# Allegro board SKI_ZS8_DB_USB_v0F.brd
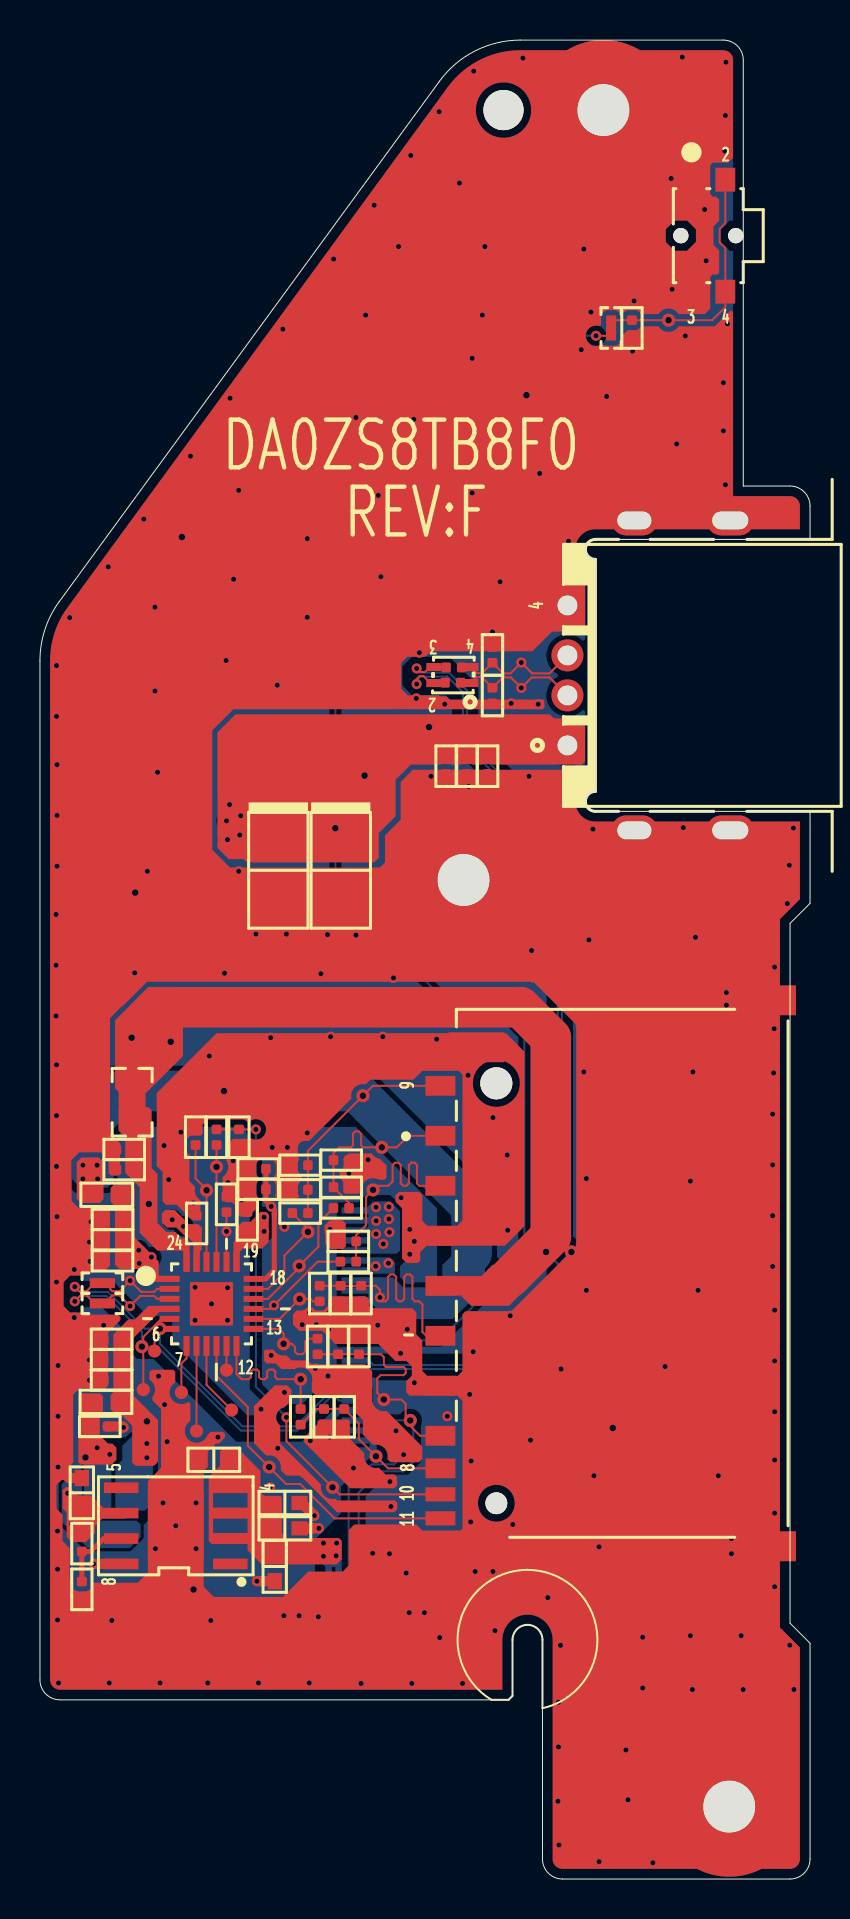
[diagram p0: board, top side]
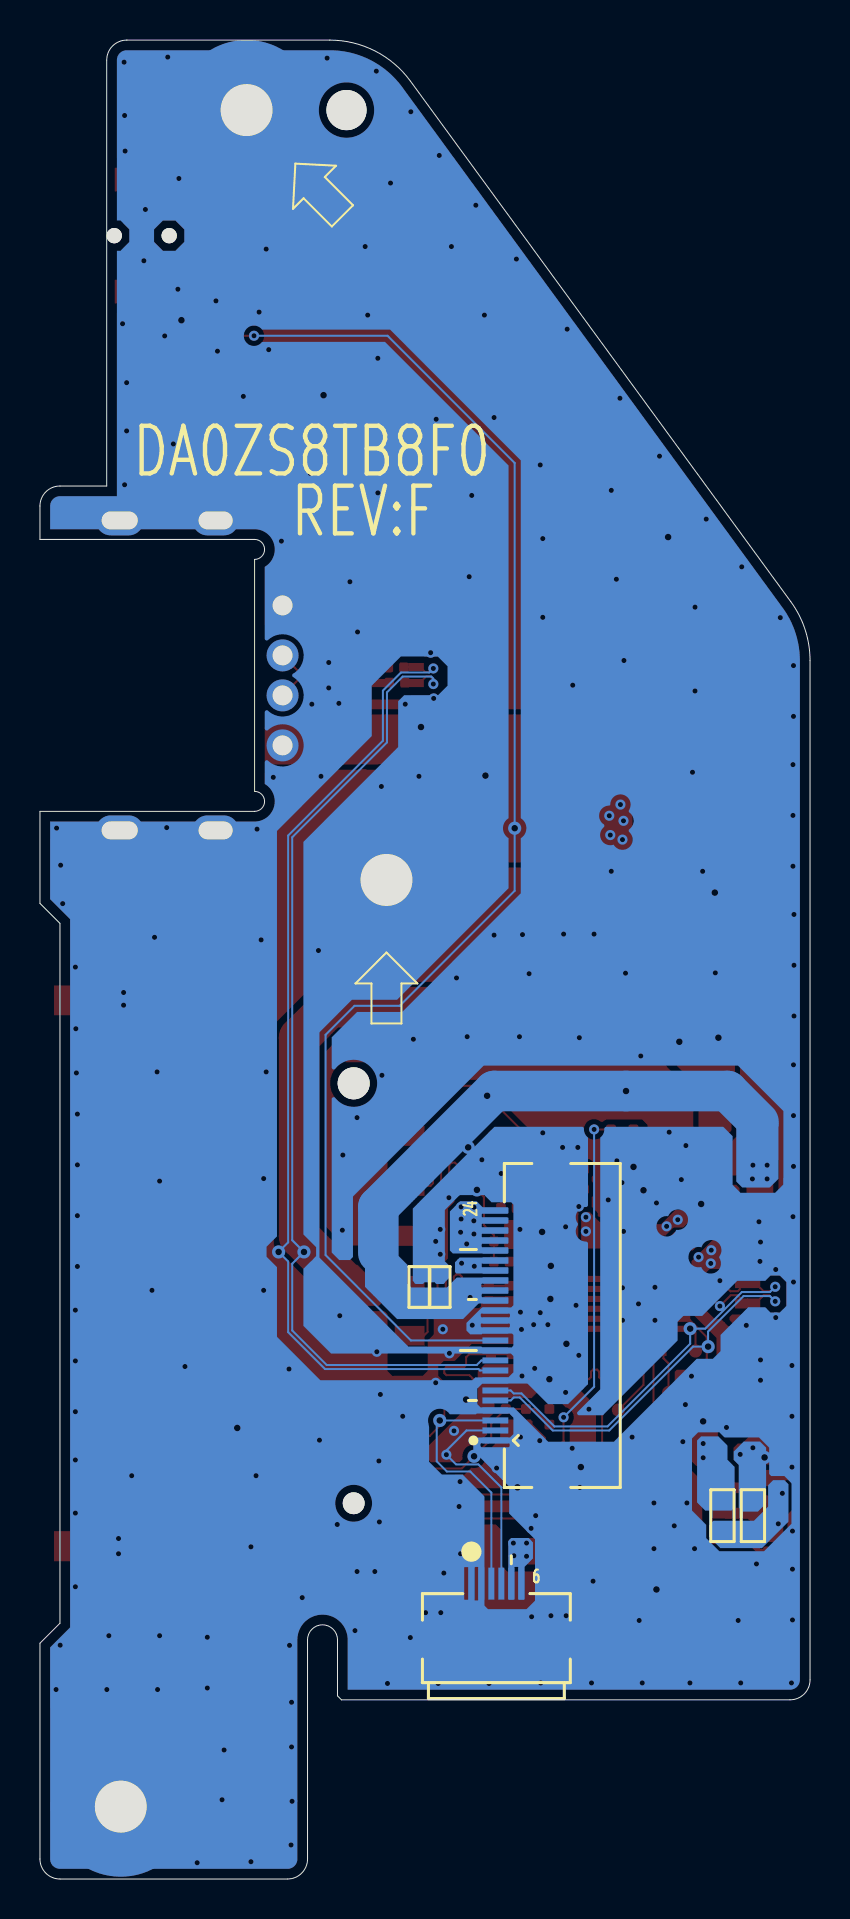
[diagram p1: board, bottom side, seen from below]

Outline 38.54 x 91.96 mm; copper layers: TOP, SGND, IN1, IN2, SVCC, IN3, SGND1, BOTTOM. Coordinates in mm from the lower left corner of the outline.
Outline path: 0,60.93 arc(0.25,62.48) 0.96,63.88 20,89.91 arc(21.77,91.42) 24.04,91.96 34.2,91.96 arc(34.91,91.67) 35.2,90.96 35.2,69.66 37.54,69.66 arc(38.25,69.37) 38.54,68.66 38.54,66.99 27.8,66.99 arc(27.3,66.49) 27.8,65.99 27.8,54.39 arc(27.3,53.89) 27.8,53.39 38.54,53.39 38.54,48.79 37.54,47.79 37.54,12.79 38.54,11.79 38.54,1 arc(38.25,0.29) 37.54,0 26.15,0 arc(25.44,0.29) 25.15,1 25.15,11.96 arc(24.4,12.71) 23.65,11.96 23.65,9.16 23.45,8.96 1,8.96 arc(0.29,9.25) 0,9.96 0,60.93

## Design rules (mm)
net group DFP-S4(4: nets USB2N7_CR USB2P7_CR
net group W4-T1B: nets SD_CLK SD_CMD SD_D0 SD_D1 SD_D2 SD_D3 SD_WP
net group W20-T123B: nets +3V3 +3V3_CR +3V3_CR_A +5V +5V_S5_USB2 VCC_SD

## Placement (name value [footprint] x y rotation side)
C1  470p/50v_4  [CC0402]  22.41 55.65 270 top
C2  0.1u/10v_4  [CC0402]  21.37 55.65 270 top
C3  150u/6.3v_3528  [CC3528]  11.93 50.44 90 top
C4  1u/6.3v_4  [CC0402]  20.32 55.65 90 top
C6  1u/16v_6  [CC0603]  8.7 20.96 180 top
C7  10u/6.3v_6  [CC0603]  12.26 17.54 0 top
C8  0.1u/50v_6  [CC0603]  12.26 18.81 0 top
C9  *0.1u/50v_6  [CC0603]  11.75 15.63 270 top
C10  10u/6.3v_6  [CC0603]  2.1 19.31 90 top
C5235  *10u/6.3v_4  [CC0402]  18.52 29.6 270 bottom
C5236  *2.2u/10v_4  [CC0402]  19.56 29.6 270 bottom
C5237  4.7u/6.3v_4  [CC0402]  3.63 31.97 0 top
C5238  0.1u/10v_4  [CC0402]  3.63 30.91 0 top
C5239  10u/6.3v_4  [CC0402]  3.63 32.98 0 top
C5240  0.1u/10v_4  [CC0402]  10.38 32.96 270 top
C5241  0.1u/10v_4  [CC0402]  7.84 32.78 270 top
C5242  2.2u/10v_4  [CC0402]  3.58 25.97 0 top
C5243  0.1u/10v_4  [CC0402]  3.58 26.99 0 top
C5244  1u/6.3v_4  [CC0402]  10.92 34.49 0 top
C5245  4.7u/6.3v_4  [CC0402]  4.22 35.47 0 top
C5246  0.1u/10v_4  [CC0402]  7.79 37.1 90 top
C5247  2.7p/50v_4  [CC0402]  16.07 29.28 90 top
C5248  0.1u/10v_4  [CC0402]  4.22 36.49 0 top
C5548  2.7p/50v_4  [CC0402]  15.97 26.63 270 top
C5549  2.7p/50v_4  [CC0402]  15.23 23.11 90 top
C5550  2.7p/50v_4  [CC0402]  13.02 35.7 0 top
C5551  2.7p/50v_4  [CC0402]  15.08 35.95 180 top
C5552  *150u/6.3v_3528  [CC3528]  15.05 50.44 90 top
C5553  68p/50v_4  [CC0402]  10.92 35.51 0 top
C5554  68p/50v_4  [CC0402]  3.58 24.95 180 top
C5555  68p/50v_4  [CC0402]  3 22.63 0 top
CN1  c14743-10409-l  [USB-C14743-10409-L-4P-L]  34.55 60.19 90 top
CN17  sd-card  [SDCARD-PSDAT4-09GLBS1NN4H0-11P]  22.84 30.29 90 top
CN5027  196033-06021-3  [AF706L-A2G1T-6P-L-SMT]  15.7 11.97 180 bottom
CN5046  usb db  [50501-02401-001-24P-L]  12.95 27.68 90 bottom
D1  *5v/0.2p_4  [CC0402]  22.65 59.18 90 top
D2  *5v/0.2p_4  [CC0402]  22.65 61.21 270 top
D9  *vport 0402 151 mv05  [RC0402]  29.63 77.56 90 top
D5006  *0.2pf/5v_4  [RC0402]  14.93 26.63 90 top
D5007  *0.2pf/5v_4  [RC0402]  14.21 23.11 270 top
D5008  *0.2pf/5v_4  [RC0402]  13.02 34.47 180 top
D5009  *0.2pf/5v_4  [RC0402]  15.08 34.59 0 top
D5010  *0.2pf/5v_4  [RC0402]  15.04 29.28 270 top
D5011  *0.2pf/5v_4  [RC0402]  15.43 31.89 180 top
D5012  *0.2pf/5v_4  [RC0402]  9.96 37.1 270 top
HOLE1  *h-c276d102p2  [H-C276D102P2]  28.2 88.46 180 bottom
HOLE2  *h-c276d102p2  [H-C276D102P2]  21.2 49.96 180 bottom
HOLE3  *h-c276d102p2  [H-C276D102P2]  34.5 3.62 0 top
HOLE4  * h-c79d79n  [H-C79D79N]  23.2 88.46 0 top
L1  mcm2012b900gbe/0.4a/90  [FILTER-MCM2012B900GBE-4P]  20.64 60.21 180 top
L5009  120ohm_2a_6  [RC0603]  3.3 23.86 180 top
NOREF  -  []  -32.21 -79.31 0 top
NOREF#2  -  []  18.59 -38.67 0 top
R1  *0_4  [RC0402]  20.67 59.83 180 top
R2  *0_4  [RC0402]  20.72 60.59 180 top
R3  31.6k/f_4  [RC0402]  2.1 14.49 90 top
R10  *short_8  [SHORT0805]  4.61 38.85 270 top
R12  *short_4  [SHORT0402]  28.59 77.56 270 top
R429  *0_6  [RC0603]  4.38 18.17 90 bottom
R5686  *0_6  [RC0603]  3.34 34.21 0 top
R5690  *short_4  [SHORT0402]  3.13 28.78 0 top
R5691  *short_4  [SHORT0402]  3.13 29.8 0 top
R5692  90.9_4  [RC0402]  13.89 26.63 270 top
R5698  33_4  [RC0402]  8.84 37.1 90 top
R6005  90.9_4  [RC0402]  13.05 23.11 270 top
R6006  90.9_4  [RC0402]  13.02 33.3 0 top
R6007  90.9_4  [RC0402]  15.08 33.55 0 top
R6008  90.9_4  [RC0402]  15.43 30.87 0 top
R6009  90.9_4  [RC0402]  14 29.28 90 top
R6010  *0_4  [RC0402]  9.34 33.74 90 top
R6011  0_6  [RC0603]  2.86 18.17 90 bottom
R6013  100k/f_4  [RC0402]  2.1 16.77 90 top
SW1  power switch  [SW-NTC316-AA1G-A160T-4P]  33.45 82.18 0 top
TP5150  *pad  [TP2675]  5.17 24.47 90 top
TP5151  *pad  [TP2675]  5.73 26.41 90 top
TP5152  *pad  [TP2675]  7.08 24.33 90 top
TP5153  *pad  [TP2675]  7.84 22.4 90 top
TP5154  *pad  [TP2675]  9.59 23.45 90 top
TP5155  *pad  [TP2675]  9.34 25.45 90 top
U1  g9661-25adjf12u  [SOP8-6-1_27-9P]  6.8 17.66 90 top
U5036  gl834l  [QFN24-4X4-5-25P-1H]  8.59 28.76 0 top

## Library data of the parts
C1 C2 C4 C5235-C5248 C5548-C5551 C5553-C5555 D1 D2 = CC0402
C3 C5552 = CC3528
C6-C10 = CC0603
CN1 = USB-C14743-10409-L-4P-L
CN17 = SDCARD-PSDAT4-09GLBS1NN4H0-11P
CN5027 = AF706L-A2G1T-6P-L-SMT
CN5046 = 50501-02401-001-24P-L
D9 D5006-D5012 R1-R3 R5692 R5698 R6005-R6010 R6013 = RC0402
HOLE1-HOLE3 = H-C276D102P2
HOLE4 = H-C79D79N
L1 = FILTER-MCM2012B900GBE-4P
L5009 R429 R5686 R6011 = RC0603
R10 = SHORT0805
R12 R5690 R5691 = SHORT0402
SW1 = SW-NTC316-AA1G-A160T-4P
TP5150-TP5155 = TP2675
U1 = SOP8-6-1_27-9P
U5036 = QFN24-4X4-5-25P-1H

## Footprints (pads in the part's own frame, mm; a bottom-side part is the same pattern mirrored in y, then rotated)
50501-02401-001-24P-L
  rect 0.305x1.295 smd: 1(-5.75,2.8) 2(-5.25,2.8) 3(-4.75,2.8) 4(-4.25,2.8) 5(-3.75,2.8) 6(-3.25,2.8) 7(-2.75,2.8) 8(-2.25,2.8) 9(-1.75,2.8) 10(-1.25,2.8) 11(-0.75,2.8) 12(-0.25,2.8) 13(0.25,2.8) 14(0.75,2.8) 15(1.25,2.8) 16(1.75,2.8) 17(2.25,2.8) 18(2.75,2.8) 19(3.25,2.8) 20(3.75,2.8) 21(4.25,2.8) 22(4.75,2.8) 23(5.25,2.8) 24(5.75,2.8)
  rect 1.803x1.397 smd: 25(-7.4,0) 26(7.4,0)
AF706L-A2G1T-6P-L-SMT
  rect 0.305x1.6 smd: 1(-1.25,2.8) 2(-0.75,2.8) 3(-0.25,2.8) 4(0.25,2.8) 5(0.75,2.8) 6(1.25,2.8)
  rect 1.803x1.397 smd: 7(-2.9,0) 8(2.9,0)
CC0402
  custom 0.12x0.12 smd: 1(0.39,0) 2(-0.39,0)
CC0603
  rect 0.813x0.711 smd: 1(0.737,0) 2(-0.737,0)
CC3528
  rect 2.032x2.413 smd: 1(1.6,0) 2(-1.6,0)
FILTER-MCM2012B900GBE-4P
  rect 0.762x0.406 smd: 1(-0.925,0.4) 2(0.925,0.4) 3(0.925,-0.4) 4(-0.925,-0.4)
H-C79D79N
  round 2.007 hole 2.007 unplated: (0,0)
H-C276D102P2
  round 7.01 hole 2.591: 1(0,0)
QFN24-4X4-5-25P-1H
  rect 0.991x0.305 smd: 1(-2.1,1.25) 2(-2.1,0.75) 3(-2.1,0.25) 4(-2.1,-0.25) 5(-2.1,-0.75) 6(-2.1,-1.25) 13(2.1,-1.25) 14(2.1,-0.75) 15(2.1,-0.25) 16(2.1,0.25) 17(2.1,0.75) 18(2.1,1.25)
  rect 0.305x0.991 smd: 7(-1.25,-2.1) 8(-0.75,-2.1) 9(-0.25,-2.1) 10(0.25,-2.1) 11(0.75,-2.1) 12(1.25,-2.1) 19(1.25,2.1) 20(0.75,2.1) 21(0.25,2.1) 22(-0.25,2.1) 23(-0.75,2.1) 24(-1.25,2.1)
  rect 2.159x2.159 smd: 25(0,0)
RC0402
  custom 0.12x0.12 smd: 1(0.39,0) 2(-0.39,0)
RC0603
  rect 0.813x0.711 smd: 1(0.737,0) 2(-0.737,0)
SDCARD-PSDAT4-09GLBS1NN4H0-11P
  round 1.092 hole 1.092 unplated: (-11.5,0)
  round 1.6 hole 1.6 unplated: (9.5,0)
  rect 0.991x1.499 smd: 1(6.875,2.8) 2(4.375,2.8) 3(1.875,2.8) 4(-0.625,2.8) 5(-3.125,2.8) 6(-5.625,2.8) 7(-8.125,2.8) 8(-9.755,2.8) 9(9.375,2.8)
  rect 0.711x1.499 smd: 10(-11.055,2.8) 11(-12.255,2.8)
  rect 1.499x2.794 smd: 12(11.3,1) 13(-13.65,1) 14(13.65,-13.6) 15(-13.65,-13.6)
SHORT0402
  rect 0.648x0.5 smd: 1(-0.39,0) 2(0.39,0)
SHORT0805
  rect 1.397x1.346 smd: 1(0.895,0) 2(-0.895,0)
SOP8-6-1_27-9P
  rect 0.533x1.727 smd: 1(-1.905,-2.73) 2(-0.635,-2.73) 3(0.635,-2.73) 4(1.905,-2.73) 5(1.905,2.73) 6(0.635,2.73) 7(-0.635,2.73) 8(-1.905,2.73)
  rect 3.302x2.794 smd: 9(0,0)
SW-NTC316-AA1G-A160T-4P
  round 0.762 hole 0.762 unplated: (-1.375,0) (1.375,0)
  rect 0.991x1.194 smd: 1(-0.85,2.8) 2(0.85,2.8) 3(-0.85,-2.8) 4(0.85,-2.8)
TP2675
  round 0.66 smd: 1(0,0)
USB-C14743-10409-L-4P-L
  round 1.6 hole 0.991: 1(-3.5,8.15) 2(-1,8.15) 3(1,8.15) 4(3.5,8.15)
  oval 1.499x2.311 hole 0.889x1.702: 5(-7.75,4.8) 6(7.75,4.8)
  oval 1.499x2.388 hole 0.889x1.803: 7(-7.75,0) 8(7.75,0)

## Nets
+3V3: C5235.1 C5236.1 CN5046.15 CN5046.16 CN5046.17 R5686.2
+3V3_CR: C5237.1 C5238.1 C5239.1 C5240.1 C5241.1 C5555.2 L5009.1 R5686.1 R6011.1 U5036.1 U5036.19 U5036.23
+3V3_CR_A: C5242.1 C5243.1 C5554.2 L5009.2 R429.1 U5036.4
+5V: C6.2 C7.2 C8.2 C9.2 CN5027.5 CN5027.6 CN5046.18 CN5046.19 U1.2 U1.3 U1.4
+5V_S5_USB2: C1.2 C2.2 C3.1 C4.1 C5552.1 CN1.1 CN5046.20 CN5046.21 CN5046.22 CN5046.23 CN5046.24
GND: C1.1 C2.1 C3.2 C4.2 C6.1 C7.1 C8.1 C9.1 C10.1 C5235.2 C5236.2 C5237.2 C5238.2 C5239.2 C5240.2 C5241.2 C5242.2 C5243.2 C5244.2 C5245.2 C5246.1 C5247.2 C5248.2 C5548.2 C5549.2 C5550.2 C5551.2 C5552.2 C5553.2 C5554.1 C5555.1 CN1.4 CN1.5 CN1.6 CN1.7 CN1.8 CN17.3 CN17.6 CN17.12 CN17.13 CN17.14 CN17.15 CN5027.1 CN5027.2 CN5027.7 CN5027.8 CN5046.1 CN5046.4 CN5046.7 CN5046.10 CN5046.12 CN5046.13 CN5046.14 CN5046.25 CN5046.26 D1.2 D2.2 D9.2 D5006.1 D5007.1 D5008.1 D5009.1 D5010.1 D5011.1 D5012.1 HOLE1.1 HOLE2.1 HOLE3.1 R3.2 R6010.1 SW1.1 SW1.3 U1.8 U1.9 U5036.25
VCC_SD: C5245.1 C5248.1 R10.1 U5036.24
CR_GPIO0: R6010.2 U5036.20
CR_VDD18: C5244.1 C5553.1 U5036.18
EL_SCL_C: CN5027.3 CN5046.3
EL_SDA_C: CN5027.4 CN5046.2
NBSWON#: CN5046.11 R12.2
POWER_BUTTON_I_EC_C: D9.1 R12.1 SW1.2 SW1.4
SD_CD#: R5698.2 U5036.21
SD_CD#_R: CN17.10 D5012.2 R5698.1
SD_CLK: R6009.2 U5036.14
SD_CLK_R: C5247.1 CN17.5 D5010.2 R6009.1
SD_CMD: R6008.2 U5036.15
SD_CMD_R: CN17.2 D5011.2 R6008.1
SD_D0: R5692.2 U5036.13
SD_D0_R: C5548.1 CN17.7 D5006.2 R5692.1
SD_D1: R6005.2 U5036.12
SD_D1_R: C5549.1 CN17.8 D5007.2 R6005.1
SD_D2: R6006.2 U5036.17
SD_D2_R: C5550.1 CN17.9 D5008.2 R6006.1
SD_D3: R6007.2 U5036.16
SD_D3_R: C5551.1 CN17.1 D5009.2 R6007.1
SD_WP: CN17.11 U5036.10
TPM_RSTZ: C5246.2 U5036.22
USB2N3: CN5046.9 L1.2 R1.1
USB2N3_CN: CN1.2 D1.1 L1.1 R1.2
USB2N7: CN5046.6 R5691.1
USB2N7_CR: R5691.2 U5036.2
USB2P3: CN5046.8 L1.3 R2.1
USB2P3_CN: CN1.3 D2.1 L1.4 R2.2
USB2P7: CN5046.5 R5690.1
USB2P7_CR: R5690.2 U5036.3
N38313166: CN17.4 R10.2
N38331581: TP5150.1 U5036.5
N38331591: TP5151.1 U5036.6
N38331627: TP5153.1 U5036.8
N38331630: TP5152.1 U5036.7
N38331633: TP5154.1 U5036.9
N38365347: C10.2 R429.2 R6011.2 R6013.1 U1.6
N38365361: R3.1 R6013.2 U1.7
N3829075310: TP5155.1 U5036.11

Pads without a net: U1 1 5

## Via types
v1: diameter 0.508, hole 0.254, TOP to BOTTOM, 307 vias
v2: diameter 0.66, hole 0.33, TOP to BOTTOM, 34 vias

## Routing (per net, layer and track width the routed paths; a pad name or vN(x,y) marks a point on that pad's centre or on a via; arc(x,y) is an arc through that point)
+3V3: length 24.4
  BOTTOM w2.032: 2.58,37.86 4.13,39.4 v2(9.21,39.4) 15.81,39.4 21.6,33.61 21.6,31.3
  vias: v1(2.15,35.7) v1(2.15,35.01) v1(2.86,35.7) v1(2.89,35.01)
+3V3_CR:
  vias: v1(2.86,21.56) v1(3.5,21.23) v1(4.94,31.45) v1(4.97,30.78) v1(5.58,31.1) v1(6.62,32.97) v1(7.18,32.64) v1(11.22,33.1) v1(11.22,32.38) v2(2.28,21.08)
+3V3_CR_A:
  vias: v1(5.35,21.78) v1(5.35,21.07) v2(5.35,22.89)
+5V:
  vias: v1(14.19,16.8) v1(14.19,16.14) v1(14.85,16.8) v1(14.82,16.16) v1(16.8,30.64) v1(17.44,30.79)
+5V_S5_USB2:
  vias: v1(9.34,52.92) v1(9.39,51.98) v1(9.49,53.73) v1(10.05,53.17) v1(10,52.21) v1(16.82,33.59) v1(16.83,32.91) v1(16.82,32.25) v1(17.19,31.76) v1(17.46,33.61) v1(17.46,33) v1(17.49,32.34) v2(16.25,55.18) v2(19.47,57.61)
GND: length 6.5
  TOP w0.508: C9.1 v1(10.86,14.89) ; C5555.1 4.13,22.63 v1(4.18,22.58) ; v1(0.91,20.6) 1.45,20.05 C10.1 ; C7.1 v1(13.96,17.54) ; v1(13.73,18.17) 13.1,18.81 C8.1 ; U1.8 v1(2.68,15.76)
  vias: v1(0.83,60.68) v1(0.83,58.14) v1(0.8,48.23) v1(0.8,45.69) v1(0.8,43.15) v1(0.83,40.72) v1(0.83,38.18) v1(0.83,35.64) v1(0.83,29.85) v1(0.85,55.73) v1(0.85,53.19) v1(0.85,50.65) v1(0.85,33.12) v1(0.91,25.68) v1(0.91,23.14) v1(0.88,17.4) v1(0.88,15.49) v1(0.88,12.95) v1(0.93,9.8) v1(1.49,63.08) v1(1.72,30.48) v1(1.72,28.08) v1(2.48,31.85) v1(2.51,30.89) v1(2.48,25.96) v1(2.48,24.94) v1(2.56,32.87) v1(3.19,27.69) v1(3.42,65.62) v1(3.47,9.8) v1(3.6,12.93) v1(4.74,45.31) v1(5.2,68) v1(5.38,50.39) v1(5.76,63.6) v1(5.76,59.41) v1(5.78,16.52) v1(5.88,55.35) v1(5.93,25.15) v1(6.01,9.8) v1(6.21,36.68) v1(6.24,23.72) v1(6.16,18.81) v1(6.44,34.98) v1(6.37,21.87) v1(6.8,17.66) v1(7.05,37.35) v1(7.53,71.15) v1(7.69,33.81) v1(7.76,29.59) v1(7.76,27.94) v1(7.81,18.81) v1(7.81,16.52) v1(8.4,9.8) v1(8.47,41.16) v1(8.59,28.76) v1(8.55,12.93) v1(8.91,22.1) v1(9.24,45.3) v1(9.31,60.93) v1(9.41,34.82) v1(9.39,29.57) v1(9.39,27.94) v1(9.51,74.05) v1(9.69,65) v1(9.67,35.92) v1(9.95,69.44) v1(9.95,50.39) v1(10.1,33.96) v1(10.81,47.25) v1(10.94,9.8) v1(11.07,23.49) v1(11.55,42.07) v1(11.52,19.58) v1(11.62,36.59) v1(11.57,26.19) v1(11.88,59.7) v1(11.9,21.54) v1(12.16,77.5) v1(12.23,32.61) v1(12.23,24.33) v1(12.21,13.17) v1(12.33,47.25) v1(12.38,36.59) v1(12.97,13.17) v1(13.12,27.72) v1(13.38,67.03) v1(13.38,63.09) v1(13.38,37.31) v1(13.5,70.71) v1(13.5,28.32) v1(13.53,21.92) v1(13.48,9.8) v1(13.83,27.72) v1(13.78,25.54) v1(13.93,13.12) v1(14.06,45.27) v1(14.39,47.23) v1(14.44,27.48) v1(14.42,25.16) v1(14.54,42.12) v1(14.52,32.49) v1(14.49,28.35) v1(14.49,22.1) v1(14.7,81.01) v1(15.46,35.28) v1(15.69,20.55) v1(15.81,73.08) v1(15.81,47.2) v1(16.07,9.78) v1(16.3,78.21) v1(16.42,35.97) v1(16.73,83.7) v1(16.65,16.29) v1(16.93,69.19) v1(16.91,27.7) v1(17.06,65.13) v1(17.16,42.12) v1(17.52,19.87) v1(17.49,16.27) v1(17.57,18.63) v1(17.69,45.06) v1(17.82,22.41) v1(17.95,81.64) v1(18.07,34.07) v1(18.05,26.29) v1(18.33,15.3) v1(18.38,27.49) v1(18.51,32.49) v1(18.51,31.24) v1(18.48,13.32) v1(18.56,86.19) v1(18.61,9.78) v1(18.71,73) v1(18.73,31.89) v1(18.74,24.82) v1(18.84,59.04) v1(18.99,61.32) v1(19.24,13.32) v1(19.57,55.14) v1(19.85,42) v1(19.98,88.38) v1(20,12.07) v1(20.26,58.75) v1(20.39,23.14) v1(21,84.81) v1(21.15,9.78) v1(21.43,40.19) v1(21.45,54.64) v1(21.5,24.23) v1(21.63,76.05) v1(21.63,69.32) v1(21.58,20.9) v1(21.56,17.86) v1(21.71,90.41) v1(21.68,26.37) v1(21.78,15.38) v1(22.14,78.21) v1(22.27,81.64) v1(22.65,62.36) v1(22.67,38.07) v1(22.67,15.38) v1(22.77,12.42) v1(23.03,64.87) v1(23.38,36.2) v1(23.41,32.44) v1(23.54,28.17) v1(23.58,58.79) v1(23.66,17.73) v1(24.17,91.06) v1(24.48,55.14) v1(24.6,46.43) v1(24.55,21.95) v1(24.93,58.75) v1(25.01,70.29) v1(25.42,14.07) v1(25.95,8.84) v1(25.95,6.6) v1(25.92,3.89) v1(25.97,1.7) v1(26.08,25.5) v1(26.05,11.68) v1(26.46,66.9) v1(26.86,55.09) v1(27.09,76.48) v1(27.22,81.51) v1(27.22,40.36) v1(27.35,35.03) v1(27.35,29.44) v1(27.47,46.96) v1(27.58,78.36) v1(27.68,52.5) v1(27.73,20.17) v1(27.98,16.61) v1(27.98,0.86) v1(28.36,74.14) v1(29.33,6.45) v1(29.43,3.96) v1(29.73,78.92) v1(29.66,76.4) v1(30.17,12.09) v1(30.17,9.55) v1(30.67,0.81) v1(31.28,25.63) v1(31.59,85.04) v1(31.64,79.5) v1(31.87,71.76) v1(32.15,91.11) v1(32.2,52.58) v1(32.3,77.17) v1(32.55,34.9) v1(32.55,12.17) v1(32.68,40.36) v1(32.66,9.47) v1(32.81,47.09) v1(32.93,29.44) v1(33.26,83.49) v1(33.34,80.92) v1(33.95,20.17) v1(34.2,74.83) v1(34.2,72.42) v1(34.33,90.86) v1(34.31,88.19) v1(34.28,86.41) v1(34.31,69.72) v1(34.41,77.77) v1(34.36,44.33) v1(34.36,43.7) v1(34.61,17.03) v1(34.61,16.27) v1(35.09,12.17) v1(35.2,9.47) v1(36.74,42.52) v1(36.72,40.31) v1(36.67,38.25) v1(36.67,35.71) v1(36.67,33.17) v1(36.67,30.63) v1(36.77,45.6) v1(36.77,28.45) v1(36.77,25.91) v1(36.77,23.37) v1(36.77,20.95) v1(36.77,18.3) v1(36.77,14.61) v1(37.4,48.78) v1(37.51,50.7) v1(37.53,11.69) v1(37.71,52.55) v1(37.74,9.47) v2(4.77,49.33) v2(7.1,67.11) v2(7.69,14.48) v2(24.35,74.2) v2(28.67,22.56)
VCC_SD:
  vias: v2(5.45,33.76)
CR_GPIO0: length 2.5
  TOP w0.102: R6010.2 v1(9.34,32.38) U5036.20
CR_VDD18: length 6.5
  TOP w0.254: U5036.18 11.3,30.01 11.73,30.44 11.73,33.26 11.73,33.48 v1(11.57,33.63) 11.31,33.89 C5244.1 C5553.1
EL_SCL_C: length 12.8
  BOTTOM w0.102: CN5046.3 v2(18.53,22.93) 18.68,22.78 18.68,20.89 18.18,20.38 17.01,20.38 15.95,19.32 CN5027.3
EL_SDA_C: length 11.3
  BOTTOM w0.102: CN5046.2 17.19,22.43 18.2,21.42 v1(18.2,21.22) 17.72,20.74 16.6,20.74 15.45,19.58 CN5027.4
NBSWON#: length 71.6
  TOP w0.102: R12.2 v1(27.83,77.17)
  BOTTOM w0.102: CN5046.11 19.97,26.93 24.25,31.2 24.25,42.22 22.8,43.66 20.54,43.66 14.78,49.42 v2(14.78,52.55) 14.78,70.81 21.14,77.17 v1(27.83,77.17)
POWER_BUTTON_I_EC_C: length 12.6
  TOP w0.102: SW1.2 34.3,82.8 34.02,82.51 34.02,81.85 34.3,81.56 SW1.4 34.3,78.61 33.65,77.95 v2(31.46,77.95) 29.63,77.95 D9.1 R12.1
SD_CD#: length 5.8
  TOP w0.102: R5698.2 8.84,36.7 v2(8.84,35.61) U5036.21
SD_CD#_R: length 27
  TOP w0.102: v1(10.81,37.49) D5012.2 R5698.1 ; v1(12.34,23.09) 12.34,21.89 v2(14.64,19.59) 14.99,19.24 19.93,19.24 19.93,19.24 CN17.10
  BOTTOM w0.102: v1(10.81,37.49) 10.81,24.62 v1(12.34,23.09)
SD_CLK: length 3.8
  TOP w0.102: R6009.2 13.66,28.89 13.54,29.01 v2(13,29.01) 12,28.01 U5036.14
SD_CLK_R: length 13
  TOP w0.102: R6009.1 D5010.2 C5247.1 16.81,29.67 17.01,29.47 v1(17.01,29.08) 17.01,28.99 17.12,28.89 17.29,28.89 17.42,29.01 17.42,30.12 17.54,30.24 17.71,30.24 17.83,30.12 17.83,29.01 17.95,28.89 18.11,28.89 18.23,29.01 18.23,30.12 18.35,30.24 18.52,30.24 18.64,30.12 18.64,29.01 18.77,28.89 18.98,28.89 19.14,28.73 19.14,27.36 19.33,27.17 19.83,27.17 CN17.5
SD_CMD: length 5.3
  TOP w0.102: U5036.15 11.53,28.51 v1(11.71,28.69) 13.89,30.87 R6008.2
SD_CMD_R: length 11.4
  TOP w0.102: R6008.1 D5011.2 15.82,32.2 16.32,32.7 16.32,34.11 v2(16.67,34.46) 16.88,34.67 17.43,34.67 17.65,34.88 17.65,35.7 17.77,35.82 17.94,35.82 18.06,35.7 18.06,34.79 18.18,34.67 18.34,34.67 18.46,34.79 18.46,35.7 18.58,35.82 18.75,35.82 18.87,35.7 18.87,34.79 19,34.67 20.04,34.67 CN17.2
SD_D0: length 4.8
  TOP w0.102: U5036.13 11.96,27.51 12.19,27.28 v2(12.19,26.76) 12.61,26.76 12.77,26.6 12.77,26.37 12.89,26.25 13.15,26.25 13.27,26.37 13.27,26.87 13.43,27.02 R5692.2
SD_D0_R: length 12
  TOP w0.102: R5692.1 D5006.2 C5548.1 17.07,26.24 17.21,26.09 17.21,25.7 17.31,25.6 18.2,25.6 18.3,25.5 18.3,25.3 18.2,25.2 17.05,25.2 16.88,25.03 16.88,24.31 v2(17.21,23.98) 18.08,23.98 18.3,23.76 18.3,22.89 19.02,22.17 19.88,22.17 CN17.7
SD_D1: length 7.7
  TOP w0.102: U5036.12 9.84,25.26 10.1,24.99 10.46,24.99 10.56,25.1 10.56,25.37 10.66,25.48 10.86,25.48 10.96,25.37 10.96,25.1 11.07,24.99 11.27,24.99 11.37,25.1 11.37,25.37 11.47,25.48 11.67,25.48 11.78,25.37 11.78,25.1 11.88,24.99 v2(13.05,24.99) R6005.2
SD_D1_R: length 9
  TOP w0.102: CN17.8 19.93,20.54 19.93,20.54 17.42,20.54 v2(16.82,21.14) 15.96,22 15.96,22.78 C5549.1 D5007.2 13.83,23.5 R6005.1
SD_D2: length 5.7
  TOP w0.102: R6006.2 13.41,32.52 v2(13.41,32.36) 12.23,31.18 12.23,30.34 11.41,29.51 U5036.17
SD_D2_R: length 11.1
  TOP w0.102: R6006.1 D5008.2 13.41,35.44 13.41,35.44 C5550.1 13.41,36.41 v2(16.16,39.17) 16.66,39.67 19.78,39.67 CN17.9
SD_D3: length 6.6
  TOP w0.102: U5036.16 11.41,29.01 12.97,30.57 v2(12.97,30.66) 13.94,31.62 13.94,32.8 R6007.2
SD_D3_R: length 10.1
  TOP w0.102: CN17.1 19.93,37.17 19.93,37.17 18.44,37.17 17.86,36.59 v2(17.11,36.59) 16.17,36.59 16.07,36.69 16.07,37.27 15.95,37.39 15.79,37.39 15.67,37.27 15.67,36.69 15.56,36.59 14.98,36.59 14.69,36.3 C5551.1 D5009.2 15.47,33.82 R6007.1
SD_WP: length 16.8
  TOP w0.102: CN17.11 14.74,18.04 13.02,19.75 12.32,19.75 v2(11.47,20.6) 10.4,21.67 10.4,23.6 8.84,25.17 U5036.10
TPM_RSTZ: length 6.1
  TOP w0.102: C5246.2 7.79,35.03 8.34,34.48 v2(8.34,34.44) U5036.22
USB2N3: length 50.2
  TOP w0.102: v1(18.85,59.76) 18.85,59.98 19.03,60.16 19.19,60.16 19.54,59.81 L1.2 20.26,59.81 R1.1
  BOTTOM w0.102: v1(18.85,59.76) 18.85,60.03 18.96,60.13 20.39,60.13 21.17,59.34 21.17,56.84 25.92,52.1 25.92,31.95 v2(25.33,31.36) 25.92,30.77 25.92,27.43 24.19,25.7 16.68,25.7 16.45,25.93 CN5046.9
USB2N3_CN: length 6.7
  TOP w0.102: R1.2 21.07,59.81 L1.1 21.86,60.11 22.11,60.11 D1.1 23.16,60.09 23.57,60.09 v1(24.09,59.56) 24.61,60.09 25.5,60.09 CN1.2
USB2N7: length 19.3
  TOP w0.102: v1(1.74,29.62) 1.97,29.39 2.33,29.39 R5691.1
  BOTTOM w0.102: CN5046.6 14.98,24.43 14.83,24.28 14.44,24.28 12.79,22.63 10.13,22.63 6,26.76 v2(6,27.52) 5.24,27.52 3.41,29.35 2.01,29.35 v1(1.74,29.62)
USB2N7_CR: length 3.8
  TOP w0.102: R5691.2 3.52,29.5 3.62,29.39 3.98,29.39 v1(4.51,29.92) 5.07,29.36 5.72,29.36 5.87,29.51 U5036.2
USB2P3: length 50.2
  TOP w0.102: R2.1 20.31,60.61 L1.3 19.52,60.61 19.27,60.36 19.03,60.36 v1(18.85,60.54)
  BOTTOM w0.102: v1(18.85,60.54) 19.06,60.33 20.47,60.33 21.38,59.43 21.38,56.92 26.12,52.18 26.12,31.84 v2(26.6,31.36) 26.12,30.88 26.12,27.35 24.27,25.5 16.59,25.5 16.52,25.43 CN5046.8
USB2P3_CN: length 6.7
  TOP w0.102: CN1.3 25.5,60.29 24.63,60.29 v1(24.09,60.83) 23.55,60.29 23.18,60.29 D2.1 22.13,60.31 21.86,60.31 L1.4 21.12,60.61 R2.2
USB2P7: length 19.4
  TOP w0.102: R5690.1 2.33,29.19 2.05,29.19 v1(1.74,28.89)
  BOTTOM w0.102: CN5046.5 14.98,23.93 14.83,24.08 14.53,24.08 12.88,22.43 10.05,22.43 5.85,26.62 v2(5.1,26.62) 5.1,27.38 3.33,29.15 2.01,29.15 v1(1.74,28.89)
USB2P7_CR: length 3.8
  TOP w0.102: U5036.3 5.87,29.01 5.72,29.16 5.02,29.16 v1(4.51,28.65) 3.97,29.19 3.63,29.19 3.52,29.08 R5690.2
N38313166: length 33.2
  TOP w2.032: 23.51,30.08 25.57,32.14 25.57,42.07 24.04,43.6 5.88,43.6
  vias: v2(4.59,42.07) v2(6.54,41.87)
N38331581: length 4.3
  TOP w0.102: U5036.5 6.08,28.01 5.17,27.1 TP5150.1
N38331591: length 1.7
  TOP w0.102: TP5151.1 5.73,27.31 5.94,27.51 U5036.6
N38331627: length 4.3
  TOP w0.102: TP5153.1 U5036.8
N38331630: length 2.4
  TOP w0.102: TP5152.1 7.08,25.78 7.34,26.04 U5036.7
N38331633: length 3.7
  TOP w0.102: U5036.9 8.34,24.71 TP5154.1
N38365347:
  vias: v1(1.39,19.29) v1(1.59,17.76)
N38365361: length 3.7
  TOP w0.254: R3.1 R6013.2 2.55,16.38 3.19,17.03 U1.7
N3829075310: length 1.2
  TOP w0.102: TP5155.1 U5036.11

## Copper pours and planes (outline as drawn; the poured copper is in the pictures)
+3V3 on TOP (solid shape): 3.18,35.85 3.18,33.99 3,33.81 2.04,33.81 1.84,34.01 1.84,35.85 2.07,36.08 2.95,36.08
+3V3 on BOTTOM (solid shape): 3.69,37.77 3.69,34.88 3.39,34.58 2.01,34.58 1.58,35.01 1.58,37.81 2.22,38.45 3.01,38.45
+3V3 on BOTTOM (solid shape): 22.27,31.23 22.27,29.61 20.66,28 17.36,28 16.59,28.78 15.14,28.78 15.1,28.81 15.1,29.05 15.14,29.08 16.4,29.08 16.43,29.12 16.43,29.24 16.4,29.28 15.13,29.28 15.1,29.31 15.1,29.55 15.13,29.58 16.42,29.58 16.45,29.62 16.45,29.74 16.41,29.78 15.13,29.78 15.1,29.8 15.1,30.08 15.1,30.08 17.68,30.08 18.18,29.58 19.97,29.58 20.14,29.76 20.14,30.71 20.97,31.53 21.97,31.53
+3V3_CR on TOP (solid shape): 3.15,24.14 3.15,23.29 2.99,23.13 2.99,22.18 3.4,21.78 3.62,21.78 3.82,21.57 3.82,20.96 3.58,20.72 2.17,20.72 2.16,20.73 2.03,20.73 1.92,20.84 1.92,24.12 2.08,24.29 3,24.29
+3V3_CR on TOP (solid shape): 11.45,33.21 11.45,31.86 11.12,31.53 10.16,31.53 9.99,31.36 9.99,30.37 9.68,30.37 9.68,31.87 9.79,31.97 9.79,32.52 10.14,32.87 10.54,32.87 11.04,33.36 11.3,33.36
+3V3_CR on TOP (solid shape): 4.74,34.53 4.74,32.09 5.94,30.88 5.94,30.21 5.99,30.16 6.98,30.16 6.98,29.86 5.66,29.86 5.02,30.51 3.97,30.51 3.76,30.72 3.76,33.65 3.53,33.87 3.53,34.56 3.69,34.72 4.55,34.72
+3V3_CR on TOP (solid shape): 7.46,32.75 7.93,32.75 8.09,32.58 8.09,31.46 7.99,31.36 7.99,30.37 7.68,30.37 7.68,31.81 7.31,32.18 7.22,32.18 6.82,32.58 6.35,32.58 6.1,32.83 6.1,33.28 6.28,33.46 6.74,33.46
+3V3_CR on BOTTOM (solid shape): 3.82,21.37 3.82,20.96 3.57,20.71 3.57,18.58 3.37,18.37 2.61,18.37 2.2,18.78 2.2,21.57 2.5,21.88 3.32,21.88
+3V3_CR on SVCC (solid shape): 12.41,33.76 12.41,32.77 13.98,31.19 13.98,30.95 13.88,30.85 7.89,30.85 6.9,29.86 6.9,21.58 5.92,20.6 2.81,20.6 2.45,20.96 2.45,22.48 3.47,23.49 3.47,31.14 6.43,34.1 12.08,34.1
+3V3_CR_A on TOP (solid shape): 6.98,28.36 5.99,28.36 4.68,27.05 4.68,24.18 5.91,22.95 5.91,20.86 5.7,20.66 4.79,20.66 4.62,20.83 4.62,22.67 4.05,23.24 3.78,23.24 3.53,23.48 3.53,24.2 3.67,24.34 3.67,27.23 4.43,27.99 4.76,27.99 5.43,28.66 5.48,28.66 6.98,28.66
+3V3_CR_A on BOTTOM (solid shape): 5.65,21.93 5.65,18.83 5.25,18.42 3.93,18.42 3.77,18.58 3.77,20.61 4.13,20.96 4.13,21.68 4.59,22.13 5.45,22.13
+5V on TOP (solid shape): 11.04,20.41 11.04,19.75 11.03,19.7 11.02,19.64 11.01,19.57 11.02,19.51 11.03,19.45 11.05,19.38 11.08,19.33 11.12,19.27 11.16,19.22 11.21,19.18 11.26,19.14 11.32,19.11 11.38,19.09 11.45,19.08 11.51,19.07 11.58,19.08 11.64,19.09 11.7,19.11 11.76,19.13 11.79,19.15 12.04,19.15 12.11,19.08 12.11,17.31 12.36,17.05 14.95,17.05 15.1,16.9 15.1,15.99 14.85,15.73 11.1,15.73 10.39,16.44 10.39,16.76 8.66,16.76 8.61,16.74 8.45,16.9 8.45,17.29 10.39,17.29 10.39,18.03 8.66,18.03 8.66,17.29 8.45,17.29 8.45,18.56 10.39,18.56 10.39,19.3 8.66,19.3 8.66,18.56 8.45,18.56 8.45,19.57 8.45,20.1 9.01,20.66 9.01,21.37 9.21,21.57 9.87,21.57
+5V on BOTTOM (solid shape): 17.77,30.85 17.77,30.35 17.7,30.28 15.14,30.28 15.1,30.31 15.1,30.55 15.14,30.58 16.4,30.58 16.43,30.62 16.43,30.77 16.42,30.78 15.11,30.78 15.1,30.79 15.1,31.07 15.12,31.08 17.53,31.08
+5V on BOTTOM (solid shape): 15.1,16.9 15.1,14 15.08,13.98 14.82,13.98 14.8,14 14.8,15.58 14.77,15.6 14.62,15.6 14.59,15.58 14.59,14 14.57,13.98 14.32,13.98 14.29,14 14.29,15.61 13.87,16.03 13.87,16.83 14.09,17.05 14.95,17.05
+5V on SVCC (solid shape): 20.49,30.66 20.49,15.58 19.42,14.51 14.14,14.51 12.66,15.99 12.66,19.74 15.2,22.28 15.2,30.49 15.74,31.02 20.13,31.02
+5V_S5_USB2 on TOP (solid shape): 25.52,58.24 25.72,58.04 26.89,58.04 27.29,57.64 27.29,55.9 27.12,55.73 22.7,55.73 22.62,55.75 22.56,55.76 22.26,55.76 22.19,55.75 22.12,55.73 21.65,55.73 21.58,55.75 21.52,55.76 21.22,55.76 21.15,55.75 21.08,55.73 20.61,55.73 20.54,55.75 20.47,55.76 20.17,55.76 20.11,55.75 20.04,55.73 18.56,55.73 17.79,54.96 17.79,53.15 16.96,52.31 16.96,51.06 16.73,50.83 10.36,50.83 10.19,51 9.45,51 8.88,51.57 8.88,53.19 8.89,53.19 8.89,54.19 8.88,54.2 8.88,57.34 9.78,58.24
+5V_S5_USB2 on BOTTOM (solid shape): 18.02,33.38 18.02,31.43 17.87,31.28 15.15,31.28 15.1,31.32 15.1,31.54 15.15,31.58 16.4,31.58 16.43,31.62 16.43,31.74 16.4,31.78 15.15,31.78 15.1,31.82 15.1,32.03 15.15,32.08 16.4,32.08 16.43,32.12 16.43,32.24 16.4,32.28 15.15,32.28 15.1,32.32 15.1,32.54 15.15,32.58 16.4,32.58 16.43,32.62 16.43,32.74 16.4,32.78 15.16,32.78 15.1,32.83 15.1,33.03 15.15,33.08 16.4,33.08 16.43,33.12 16.43,33.24 16.4,33.28 15.15,33.28 15.1,33.33 15.1,33.54 15.15,33.58 16.37,33.58 16.68,33.89 17.52,33.89
+5V_S5_USB2 on SVCC (solid shape): 14.86,53.83 14.86,46.27 20.49,40.64 20.49,31.79 20.23,31.53 15.53,31.53 15.17,31.17 14.73,31.17 14.5,31.4 14.49,31.4 12.92,32.98 12.92,39.55 7.53,44.94 7.53,53.8 8.43,54.7 14,54.7
GND on TOP (solid shape): 9.64,29.8 9.64,27.72 9.62,27.7 7.56,27.7 7.53,27.72 7.53,29.8 7.56,29.83 9.62,29.83
GND on TOP (solid shape): 15.31,32.78 15.31,31.63 15.18,31.51 14.54,31.51 14.28,31.77 14.28,32.26 14.24,32.29 14.24,32.67 14.51,32.94 14.65,32.94 14.66,32.95 15.13,32.95
GND on TOP (solid shape): 15.51,22.89 15.51,22.01 16.25,21.28 16.24,21.25 16.4,20.73 16.93,20.56 16.95,20.57 17.29,20.23 17.74,20.23 17.87,20.1 17.87,19.68 17.73,19.54 15.52,19.54 13.22,21.84 13.22,22.08 13.88,22.74 13.88,22.88 13.98,22.98 15.42,22.98
GND on TOP (solid shape): 16.61,36.28 16.79,36.1 17.03,36.01 17.34,35.69 17.34,35.07 17.24,34.97 16.96,34.97 16.35,34.95 16.09,34.4 15.97,34.27 15.25,34.27 15.18,34.35 15.18,34.75 15.13,34.93 14.99,35.06 14.99,35.35 15.14,35.48 15.19,35.67 15.19,35.95 15.19,35.98 15.19,36.02 15.45,36.28
GND on TOP (solid shape): 12.59,24.47 12.59,23.94 12.24,23.59 11.84,23.2 12.03,22.68 12.03,21.77 14.07,19.72 14.07,19.7 14.23,19.17 14.75,19.01 14.78,19.02 14.87,18.93 17.76,18.93 17.88,18.81 17.88,18.5 17.72,18.34 14.87,18.34 13.15,20.06 13.11,20.06 13,20.17 12.33,20.17 12.04,20.46 12.05,20.49 11.88,21.01 11.36,21.17 11.33,21.17 10.71,21.79 10.71,23.65 11.75,24.69 12.37,24.69
GND on TOP (solid shape): 11.68,26.48 11.95,26.23 12.3,26.19 12.33,26.19 12.59,25.94 13.43,25.94 13.56,25.8 13.74,25.75 16.27,25.75 16.63,25.39 16.63,24.07 16.63,24.06 16.81,23.55 17.32,23.4 17.35,23.41 19.14,21.62 19.14,21.01 18.97,20.84 17.55,20.84 17.39,21 17.39,21.03 17.23,21.55 16.7,21.71 16.68,21.71 16.16,22.23 16.16,22.95 15.79,23.32 15.79,23.86 15.6,24.05 13.94,24.05 13.6,24.38 13.6,24.82 13.41,25.45 12.76,25.5 12.08,25.5 11.8,25.78 11.34,25.78 11.22,25.91 11.22,26.4 11.29,26.48
GND on TOP (solid shape): outline of 374 points within 5.84,30.81 24.25,42.3
GND on TOP (solid shape): outline of 850 points within 0.51,0.51 38.03,91.45
GND on BOTTOM (solid shape): outline of 1387 points within 0.51,0.51 38.03,91.45
GND on SGND (solid shape): outline of 479 points within 0.51,0.51 38.03,91.45
GND on IN1 (solid shape): outline of 1978 points within 0.51,0.51 38.03,91.45
GND on IN2 (solid shape): outline of 1971 points within 0.51,0.51 38.03,91.45
GND on SVCC (solid shape): outline of 453 points within 1.02,1.02 37.53,90.94
GND on IN3 (solid shape): outline of 1969 points within 0.51,0.51 38.03,91.45
GND on SGND1 (solid shape): outline of 479 points within 0.51,0.51 38.03,91.45
VCC_SD on TOP (solid shape): 5.59,38.45 5.59,35.55 5.88,35.26 5.88,32.8 6.33,32.36 6.77,32.36 7.09,32.04 7.31,32.04 7.49,31.86 7.49,30.37 7.18,30.37 7.18,31.36 7.11,31.43 5.87,31.43 4.99,32.31 4.99,34.59 4.27,35.32 4.27,37.09 3.94,37.42 3.94,38.49 4.05,38.6 5.44,38.6
N38313166 on TOP (solid shape): 7.16,44.05 7.16,41.15 5.33,39.33 3.97,39.33 3.76,39.54 3.76,42.94 5.43,44.61 6.59,44.61
N38313166 on TOP (solid shape): 24.15,30.27 24.15,29.34 23.47,28.66 21.58,28.66 21.06,29.18 19.44,29.18 19.38,29.24 19.38,30.08 19.45,30.15 22.09,30.15 22.65,30.71 23.71,30.71
N38365347 on TOP (solid shape): 1.89,19.19 2.55,19.19 3.22,18.53 4.28,18.53 4.33,18.47 4.33,18.07 4.29,18.03 3.2,18.03 3.2,18.02 3.11,18.02 2.76,17.66 2.76,17.31 2.3,16.85 1.59,16.85 1.34,17.1 1.34,18.32 1.13,18.53 1.13,19.44 1.28,19.59 1.49,19.59
N38365347 on BOTTOM (solid shape): 2.1,19.69 2.1,18.63 2.81,17.92 4.84,17.92 5.04,17.71 5.04,17.1 4.49,16.54 2.4,16.54 1.08,17.87 1.08,19.74 1.28,19.95 1.84,19.95

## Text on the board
Ref Des/Silkscreen Bottom: REV:F | DA0ZS8TB8F0
Ref Des/Silkscreen Top: DA0ZS8TB8F0 | REV:F
User.12: +3V3_CR | +5V_S5_USB | +5V
User.45: FIGURE | TYPE | Circle | Oblong | SIZE | 10.0 | 39.0 | 102.0 | 30.0 | 43.0 | 63.0 | 79.0 | 67.0x35.0 | 71.0x35.0 | DRILL CHART: TOP to BOTTOM | ALL UNITS ARE IN MILS | PLATED | NON-PLATED | ROTATION | - | 0.000 | QTY | 298 | 4 | 3 | 2 | 1 | 310 | TOTAL HOLES:
